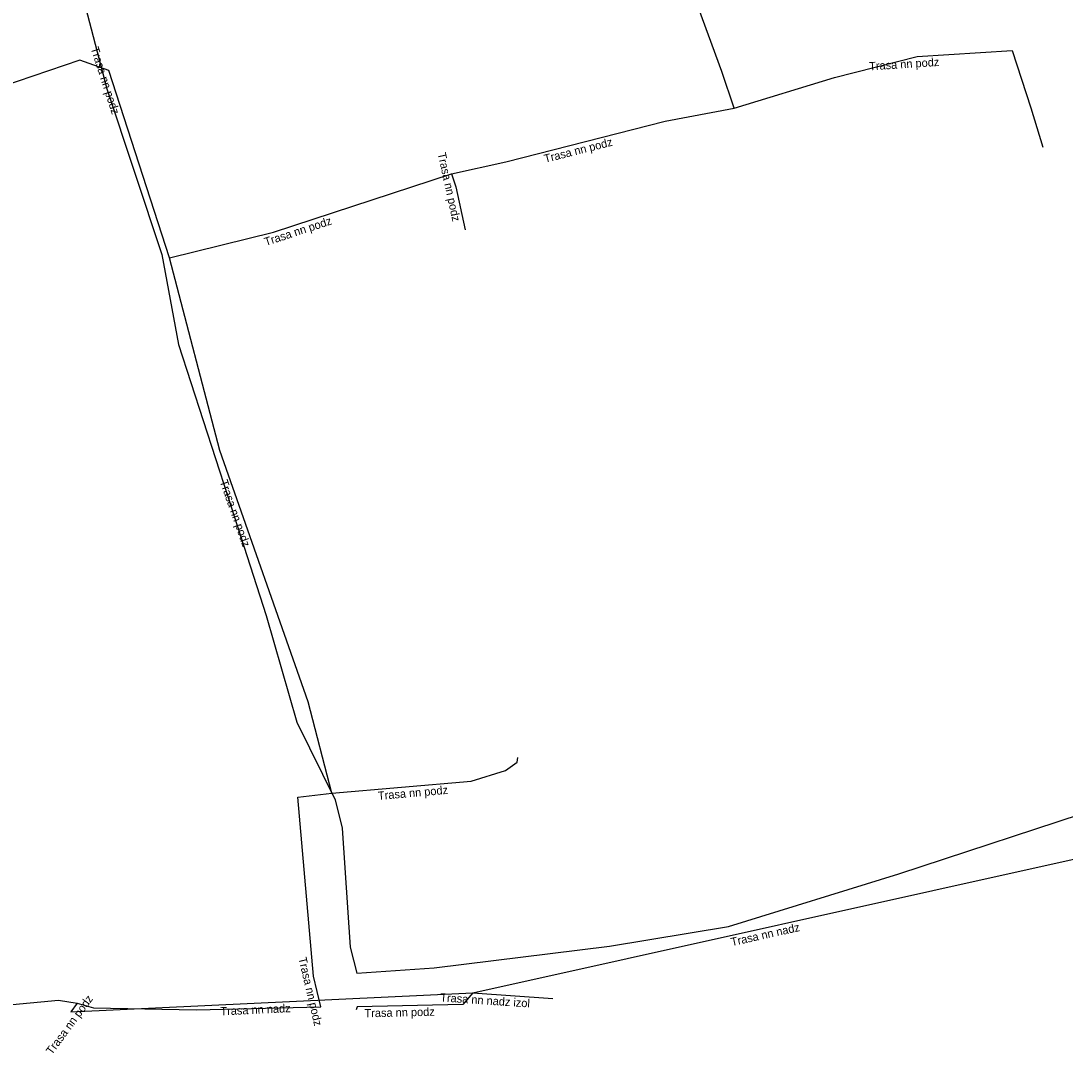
# Model space of a CAD drawing. Extents: x -682605 to -681948, y -1059884 to -1059661.
# Drawn here: x -682444.9 to -682381.3, y -1059848.4 to -1059785.6 of the extents above; entities that cross this region are included whole.
import ezdxf

# ---------------------------------------------------------------- set-up
doc = ezdxf.new("R2010")
doc.units = 0
for name, color, linetype in [('Popiskový text - Ostatní atributy Trasy', 7, 'Continuous'), ('Spojnice NN', 7, 'Continuous'), ('Spojnice VN', 7, 'Continuous')]:
    doc.layers.add(name, color=color, linetype=linetype)

msp = doc.modelspace()

# ---------------------------------------------------------------- linework, layer by layer
at = {"layer": 'Spojnice NN'}
for points in [[(-682401.45, -1059790.87), (-682402.21, -1059788.64), (-682404.64, -1059781.98), (-682407.73, -1059771.22), (-682408.44, -1059769.05), (-682410.2, -1059769.05), (-682412.64, -1059770.1)], [(-682401.45, -1059790.87), (-682395.35, -1059788.99), (-682390.33, -1059787.73), (-682384.55, -1059787.36), (-682383.4, -1059790.85), (-682382.67, -1059793.24)], [(-682435.82, -1059799.97), (-682439.5, -1059788.57), (-682441.27, -1059787.95), (-682447.96, -1059790.21)], [(-682418.65, -1059794.86), (-682415.35, -1059794.14), (-682405.66, -1059791.66), (-682401.45, -1059790.87)], [(-682435.82, -1059799.97), (-682429.48, -1059798.42), (-682418.65, -1059794.86)], [(-682418.65, -1059794.86), (-682418.39, -1059795.66), (-682417.82, -1059798.28)], [(-682425.93, -1059832.56), (-682427.37, -1059826.99), (-682432.74, -1059811.69), (-682435.82, -1059799.97)], [(-682425.93, -1059832.56), (-682417.45, -1059831.82), (-682415.36, -1059831.18), (-682414.66, -1059830.67), (-682414.62, -1059830.39)], [(-682441.43, -1059845.33), (-682440.43, -1059845.62), (-682434.2, -1059845.75), (-682426.61, -1059845.56), (-682427.05, -1059843.69), (-682428.01, -1059832.79), (-682425.93, -1059832.56)], [(-682417.36, -1059844.71), (-682379.97, -1059836.39)], [(-682462.45, -1059846.41), (-682454.44, -1059846.26), (-682442.57, -1059845.16), (-682441.43, -1059845.33)], [(-682441.82, -1059845.86), (-682417.36, -1059844.71)], [(-682417.36, -1059844.71), (-682417.96, -1059845.41), (-682424.39, -1059845.56), (-682424.46, -1059845.74)], [(-682417.36, -1059844.71), (-682412.496, -1059845.043)], [(-682441.43, -1059845.33), (-682441.82, -1059845.86)]]:
    msp.add_lwpolyline(points, dxfattribs=at)
at = {"layer": 'Spojnice VN'}
for points in [[(-682442.22, -1059779.72), (-682439.62, -1059789.68), (-682436.28, -1059799.78), (-682435.27, -1059805.25), (-682432.27, -1059814.5), (-682429.93, -1059821.74), (-682428.06, -1059828.23), (-682425.74, -1059832.96), (-682425.31, -1059834.68), (-682424.81, -1059841.93), (-682424.42, -1059843.52), (-682419.71, -1059843.18)], [(-682419.71, -1059843.18), (-682409.04, -1059841.86), (-682401.8, -1059840.66), (-682391.43, -1059837.47), (-682378.96, -1059833.37), (-682366.87, -1059827.88), (-682350.77, -1059821.14), (-682334.98, -1059814.51), (-682322.31, -1059809.45), (-682316.78, -1059807.47), (-682307.06, -1059804.21), (-682298.09, -1059802), (-682285.23, -1059800.25), (-682273.9, -1059799.1), (-682259.98, -1059797.91), (-682246.72, -1059796.96), (-682230, -1059795.42), (-682225.98, -1059795.71), (-682224.89, -1059801.14), (-682222.94, -1059818.12), (-682221.467, -1059834.279)]]:
    msp.add_lwpolyline(points, dxfattribs=at)

# ---------------------------------------------------------------- texts
at = {"layer": 'Popiskový text - Ostatní atributy Trasy'}
for s, rotation, p in [('Trasa nn podz', 287.89044, (-682440.618, -1059787.222)), ('Trasa nn podz', 3.66273, (-682393.227, -1059788.567)), ('Trasa nn podz', 14.35578, (-682412.954, -1059794.198)), ('Trasa nn podz', 282.27385, (-682419.498, -1059793.621)), ('Trasa nn podz', 18.19655, (-682429.952, -1059799.259)), ('Trasa nn podz', 289.34007, (-682432.764, -1059813.583)), ('Trasa nn podz', 4.98723, (-682423.108, -1059832.967)), ('Trasa nn nadz', 12.54503, (-682401.596, -1059841.868)), ('Trasa nn podz', 283.24052, (-682427.974, -1059842.6)), ('Trasa nn podz', 53.65254, (-682442.967, -1059848.515)), ('Trasa nn nadz izol', 356.08352, (-682419.352, -1059845.226)), ('Trasa nn nadz', 2.69181, (-682432.703, -1059846.083)), ('Trasa nn podz', 1.33636, (-682423.942, -1059846.199))]:
    msp.add_text(s, height=0.5, rotation=rotation, dxfattribs=at).set_placement(p)

doc.saveas('drawing.dxf')
